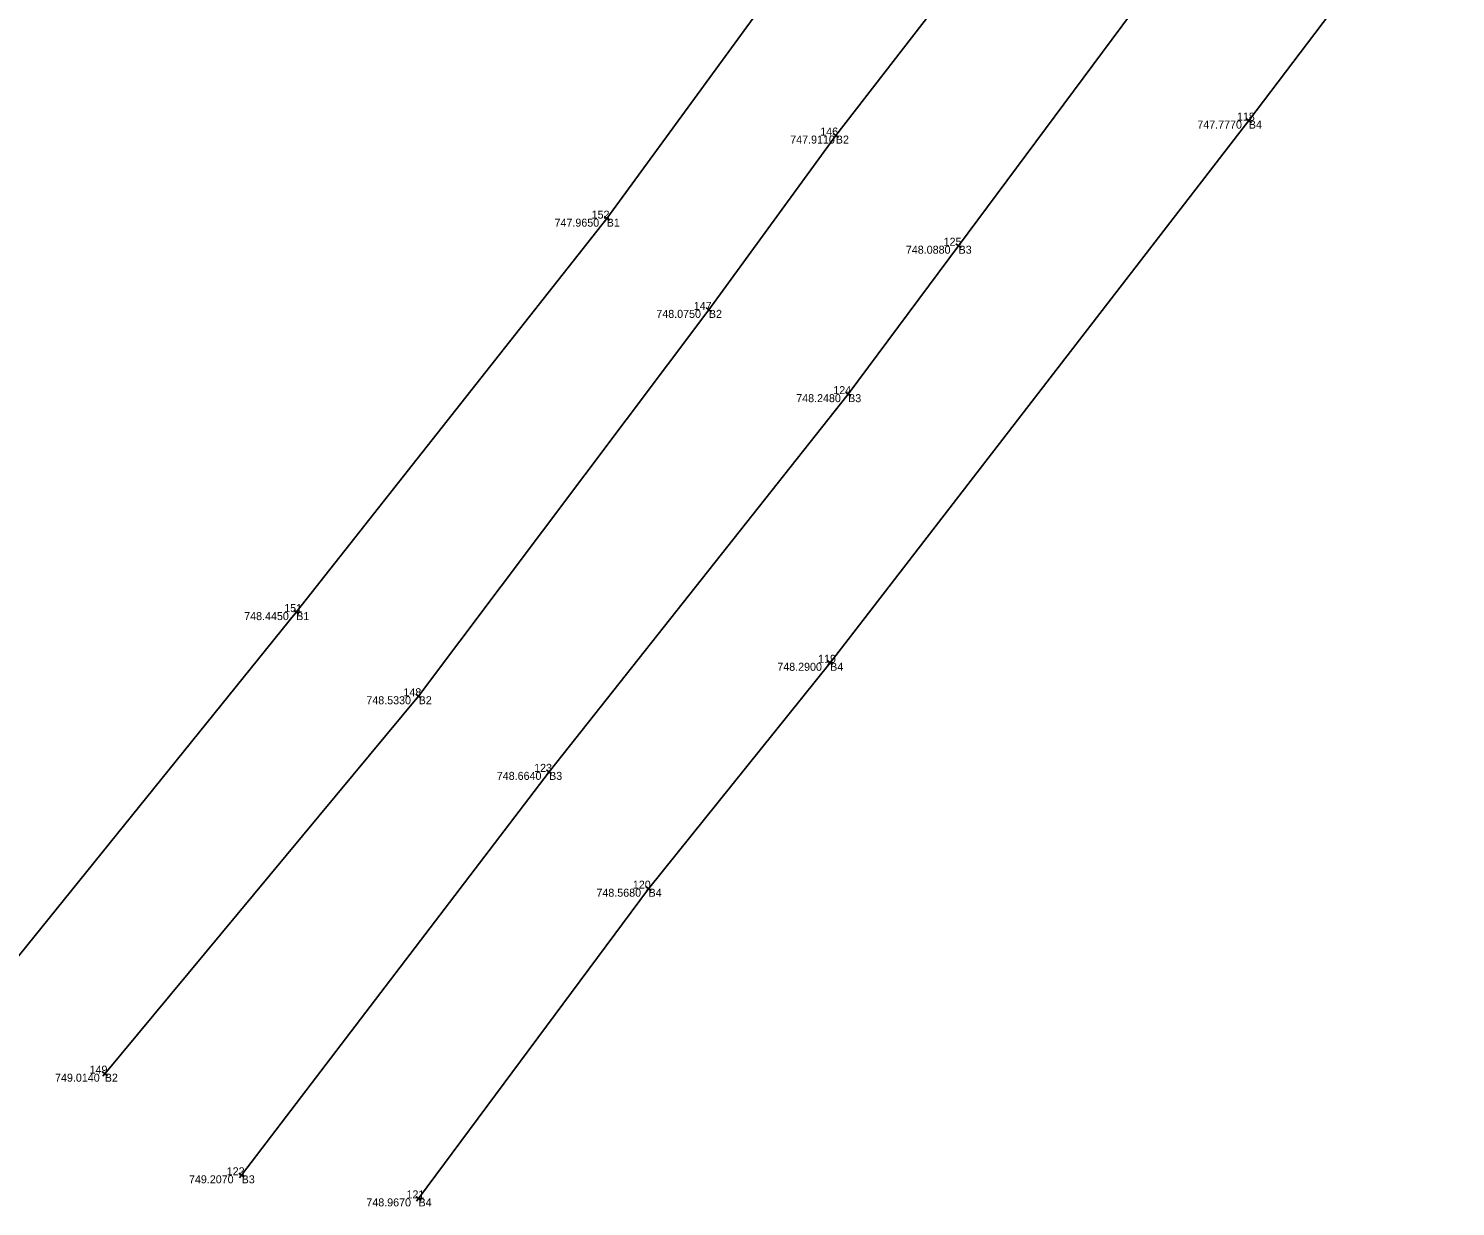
# Model space of a CAD drawing. Extents: x 1857337 to 1857837, y 693958 to 694371.
# Drawn here: x 1857509.4 to 1857616.4, y 694113.2 to 694201.5 of the extents above; entities that cross this region are included whole.
import ezdxf

# ---------------------------------------------------------------- set-up
doc = ezdxf.new("R2010")
doc.units = 0
for name, color, linetype in [('BR_X_SV_Pier_Cap_Bottom', 7, 'Continuous'), ('SV_X_Text_Comment', 7, 'Continuous'), ('SV_X_Text_Description', 7, 'Continuous'), ('SV_X_Text_Name', 7, 'Continuous'), ('UT_X_Electric_Cells', 7, 'Continuous')]:
    doc.layers.add(name, color=color, linetype=linetype)

msp = doc.modelspace()

# ---------------------------------------------------------------- linework, layer by layer
at = {"layer": 'BR_X_SV_Pier_Cap_Bottom'}
for p, q in [((1857601.1, 694194.42), (1857600.7, 694194.73)), ((1857601.05, 694194.77), (1857600.75, 694194.38)), ((1857600.9, 694194.58), (1857600.9, 694194.58)), ((1857570.14, 694193.31), (1857569.75, 694193.62)), ((1857570.1, 694193.66), (1857569.79, 694193.27)), ((1857569.94, 694193.46), (1857569.94, 694193.46)), ((1857552.96, 694187.08), (1857552.56, 694187.38)), ((1857552.91, 694187.43), (1857552.61, 694187.03)), ((1857552.76, 694187.23), (1857552.76, 694187.23)), ((1857579.34, 694185.05), (1857578.94, 694185.35)), ((1857579.29, 694185.4), (1857578.99, 694185)), ((1857579.14, 694185.2), (1857579.14, 694185.2)), ((1857560.62, 694180.24), (1857560.22, 694180.54)), ((1857560.57, 694180.59), (1857560.27, 694180.19)), ((1857560.42, 694180.39), (1857560.42, 694180.39)), ((1857571.06, 694173.92), (1857570.66, 694174.22)), ((1857571.01, 694174.27), (1857570.71, 694173.87)), ((1857570.86, 694174.07), (1857570.86, 694174.07)), ((1857529.68, 694157.57), (1857529.29, 694157.88)), ((1857529.64, 694157.92), (1857529.33, 694157.53)), ((1857529.48, 694157.73), (1857529.48, 694157.73)), ((1857569.7, 694153.78), (1857569.31, 694154.09)), ((1857569.66, 694154.13), (1857569.35, 694153.74)), ((1857569.51, 694153.93), (1857569.51, 694153.93)), ((1857538.86, 694151.27), (1857538.46, 694151.57)), ((1857538.81, 694151.62), (1857538.51, 694151.22)), ((1857538.66, 694151.42), (1857538.66, 694151.42)), ((1857548.63, 694145.59), (1857548.24, 694145.9)), ((1857548.59, 694145.94), (1857548.28, 694145.55)), ((1857548.44, 694145.75), (1857548.44, 694145.75)), ((1857556.09, 694136.83), (1857555.7, 694137.15)), ((1857556.05, 694137.18), (1857555.74, 694136.8)), ((1857555.9, 694136.99), (1857555.9, 694136.99)), ((1857515.32, 694122.96), (1857514.94, 694123.28)), ((1857515.29, 694123.31), (1857514.97, 694122.93)), ((1857515.13, 694123.12), (1857515.13, 694123.12)), ((1857525.58, 694115.35), (1857525.19, 694115.66)), ((1857525.54, 694115.7), (1857525.23, 694115.31)), ((1857525.39, 694115.5), (1857525.39, 694115.5)), ((1857538.85, 694113.62), (1857538.45, 694113.92)), ((1857538.8, 694113.97), (1857538.5, 694113.57)), ((1857538.65, 694113.77), (1857538.65, 694113.77))]:
    msp.add_line(p, q, dxfattribs=at)
at = {"layer": 'UT_X_Electric_Cells'}
for points in [[(1857688.76, 694366.46), (1857664.26, 694336.58), (1857640.4, 694304), (1857624.29, 694283.66), (1857611.11, 694265.29), (1857596.56, 694246.69), (1857577.55, 694221.21), (1857552.76, 694187.23), (1857529.48, 694157.73), (1857506.44, 694129.2)], [(1857700.07, 694362.04), (1857689.25, 694348.99), (1857682.84, 694339.86), (1857667.65, 694320.73), (1857658.45, 694307.7), (1857647.3, 694293.67), (1857639.92, 694285.28), (1857631.25, 694272.58), (1857620.54, 694259.56), (1857609.95, 694246.13), (1857585.77, 694213.92), (1857569.94, 694193.46), (1857560.42, 694180.39), (1857538.66, 694151.42), (1857515.13, 694123.12)], [(1857711.16, 694357.22), (1857703.2, 694345.96), (1857690.71, 694330.85), (1857675.14, 694311.61), (1857665.25, 694297.05), (1857650.19, 694279.11), (1857639.82, 694265.06), (1857626.46, 694247.57), (1857616.28, 694234.21), (1857602.42, 694215.52), (1857593.56, 694204.62), (1857579.14, 694185.2), (1857570.86, 694174.07), (1857548.44, 694145.75), (1857525.39, 694115.5)], [(1857720.32, 694352.91), (1857704.98, 694332.67), (1857684.03, 694304.99), (1857662.01, 694274.86), (1857649.39, 694258.92), (1857636.49, 694241.06), (1857621.4, 694221.62), (1857600.9, 694194.58), (1857569.51, 694153.93), (1857555.9, 694136.99), (1857538.65, 694113.77)]]:
    msp.add_lwpolyline(points, dxfattribs=at)

# ---------------------------------------------------------------- texts
at = {"layer": 'SV_X_Text_Comment'}
for s, p in [('B4', (1857600.9, 694193.98)), ('B2', (1857569.94, 694192.86)), ('B1', (1857552.76, 694186.63)), ('B3', (1857579.14, 694184.6)), ('B2', (1857560.42, 694179.79)), ('B3', (1857570.86, 694173.47)), ('B1', (1857529.48, 694157.13)), ('B4', (1857569.51, 694153.33)), ('B2', (1857538.66, 694150.82)), ('B3', (1857548.44, 694145.15)), ('B4', (1857555.9, 694136.39)), ('B2', (1857515.13, 694122.52)), ('B3', (1857525.39, 694114.9)), ('B4', (1857538.65, 694113.17))]:
    msp.add_text(s, height=0.6, dxfattribs=at).set_placement(p)
at = {"layer": 'SV_X_Text_Description'}
for s, p in [('747.7770', (1857597.04, 694193.98)), ('747.9110', (1857566.52, 694192.86)), ('747.9650', (1857548.85, 694186.63)), ('748.0880', (1857575.19, 694184.6)), ('748.0750', (1857556.48, 694179.79)), ('748.2480', (1857566.97, 694173.47)), ('748.4450', (1857525.58, 694157.13)), ('748.2900', (1857565.55, 694153.33)), ('748.5330', (1857534.74, 694150.82)), ('748.6640', (1857544.52, 694145.15)), ('748.5680', (1857551.99, 694136.39)), ('749.0140', (1857511.4, 694122.52)), ('749.2070', (1857521.44, 694114.9)), ('748.9670', (1857534.74, 694113.17))]:
    msp.add_text(s, height=0.6, dxfattribs=at).set_placement(p)
at = {"layer": 'SV_X_Text_Name'}
for s, p in [('118', (1857600.01, 694194.58)), ('146', (1857568.77, 694193.46)), ('152', (1857551.63, 694187.23)), ('125', (1857578.02, 694185.2)), ('147', (1857559.29, 694180.39)), ('124', (1857569.75, 694174.07)), ('151', (1857528.58, 694157.73)), ('119', (1857568.61, 694153.93)), ('148', (1857537.52, 694151.42)), ('123', (1857547.32, 694145.75)), ('120', (1857554.72, 694136.99)), ('149', (1857513.99, 694123.12)), ('122', (1857524.27, 694115.5)), ('121', (1857537.75, 694113.77))]:
    msp.add_text(s, height=0.6, dxfattribs=at).set_placement(p)

doc.saveas('drawing.dxf')
